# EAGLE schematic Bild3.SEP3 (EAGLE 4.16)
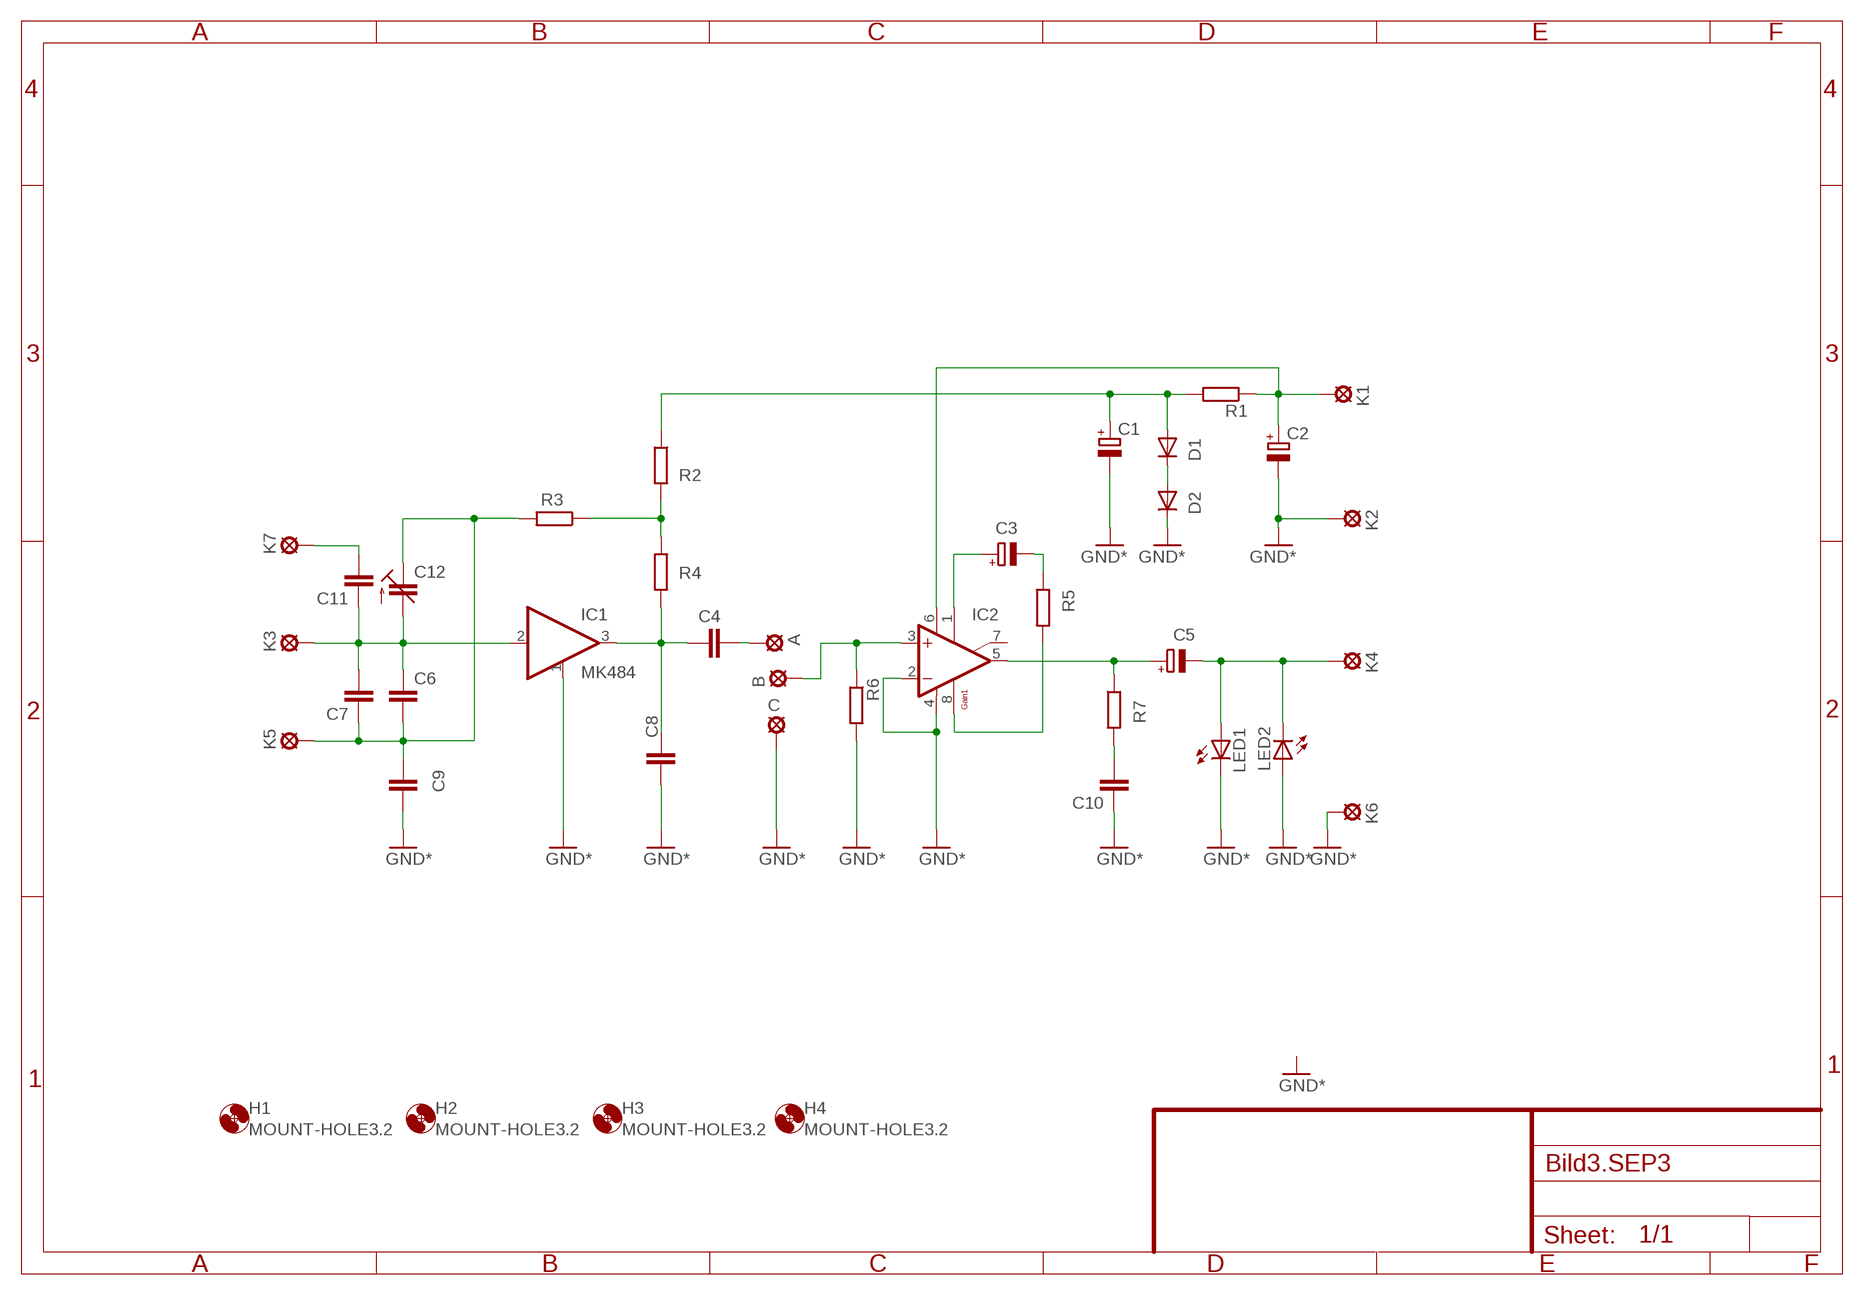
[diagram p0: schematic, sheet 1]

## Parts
A  LSP13  [LSP13]
B  LSP13  [LSP13]
C  LSP13  [LSP13]
C1  CPOL-EUE5-10.5  [E5-10,5]
C2  CPOL-EUE5-10.5  [E5-10,5]
C3  CPOL-EUE2.5-5  [E2,5-5]
C4  C-EU050-035X075  [C050-035X075]
C5  CPOL-EUE5-10.5  [E5-10,5]
C6  C-EU050-030X075  [C050-030X075]
C7  C-EU050-030X075  [C050-030X075]
C8  C-EU050-035X075  [C050-035X075]
C9  C-EU050-035X075  [C050-035X075]
C10  C-EU050-035X075  [C050-035X075]
C11  C-EU050-030X075  [C050-030X075]
C12  C-TRIMM3040.427  [CTRIM3040.427]
D1  1N4148  [DO35-10]
D2  1N4148  [DO35-10]
H1  MOUNT-HOLE3.2  [3,2]
H2  MOUNT-HOLE3.2  [3,2]
H3  MOUNT-HOLE3.2  [3,2]
H4  MOUNT-HOLE3.2  [3,2]
IC1  MK484  [TO92]
IC2  LM386NDIL08  [DIL08@1]
K1  LSP13  [LSP13]
K2  LSP13  [LSP13]
K3  LSP13  [LSP13]
K4  LSP13  [LSP13]
K5  LSP13  [LSP13]
K6  LSP13  [LSP13]
K7  LSP13  [LSP13]
LED1  LED5MM  [LED5MM]
LED2  LED5MM  [LED5MM]
R1  R-EU_0207/10E  [0207/10E]
R2  R-EU_0207/10E  [0207/10E]
R3  R-EU_0207/10E  [0207/10E]
R4  R-EU_0207/10E  [0207/10E]
R5  R-EU_0207/10E  [0207/10E]
R6  R-EU_0207/10E  [0207/10E]
R7  R-EU_0207/10E  [0207/10E]

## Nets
GND: C1.- C2.- C8.2 C9.1 C10.2 C.MP D2.C IC1.1(-IN) IC2.2(-IN) IC2.4(GND) K2.MP K6.MP LED1.K(C) LED2.A R6.2 ; supply symbol labelled GND*
N$1: C2.+ IC2.6(V+) K1.MP R1.1
N$2: C6.2 C7.1 C11.2 C12.2(A) IC1.2(+IN) K3.MP
N$3: D1.C D2.A
N$4: C4.1 C8.1 IC1.3(OUT) R4.2
N$5: C3.+ IC2.1(GAIN)
N$6: C3.- R5.1
N$7: C11.1 K7.MP
N$8: R2.2 R3.1 R4.1
N$9: IC2.8(GAIN1) R5.2
N$10: C1.+ D1.A R1.2 R2.1
N$11: A.MP C4.2
N$12: C5.+ IC2.5(OUT) R7.1
N$13: B.MP IC2.3(+IN) R6.1
N$15: C5.- K4.MP LED1.A LED2.K(C)
N$18: C6.1 C7.2 C9.2 C12.1A(E) K5.MP R3.2
N$23: C10.1 R7.2
Unconnected: IC2.7(BYPASS)

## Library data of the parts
A B C K1-K7 = solpad:LSP13: SOLDER PAD
C1-C3 C5 = rcl:CPOL-EU: POLARIZED CAPACITOR, European symbol
C4 C6-C11 = rcl:C-EU: CAPACITOR, European symbol
C12 = rcl:C-TRIMM: Trimm capacitor
D1 D2 = diode:1N4148: DIODE
H1-H4 = holes:MOUNT-HOLE: MOUNTING HOLE with drill center marker
IC1 = FMW:MK484
IC2 = linear:*386N
LED1 LED2 = led:LED: LED
R1-R7 = rcl:R-EU_: RESISTOR, European symbol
